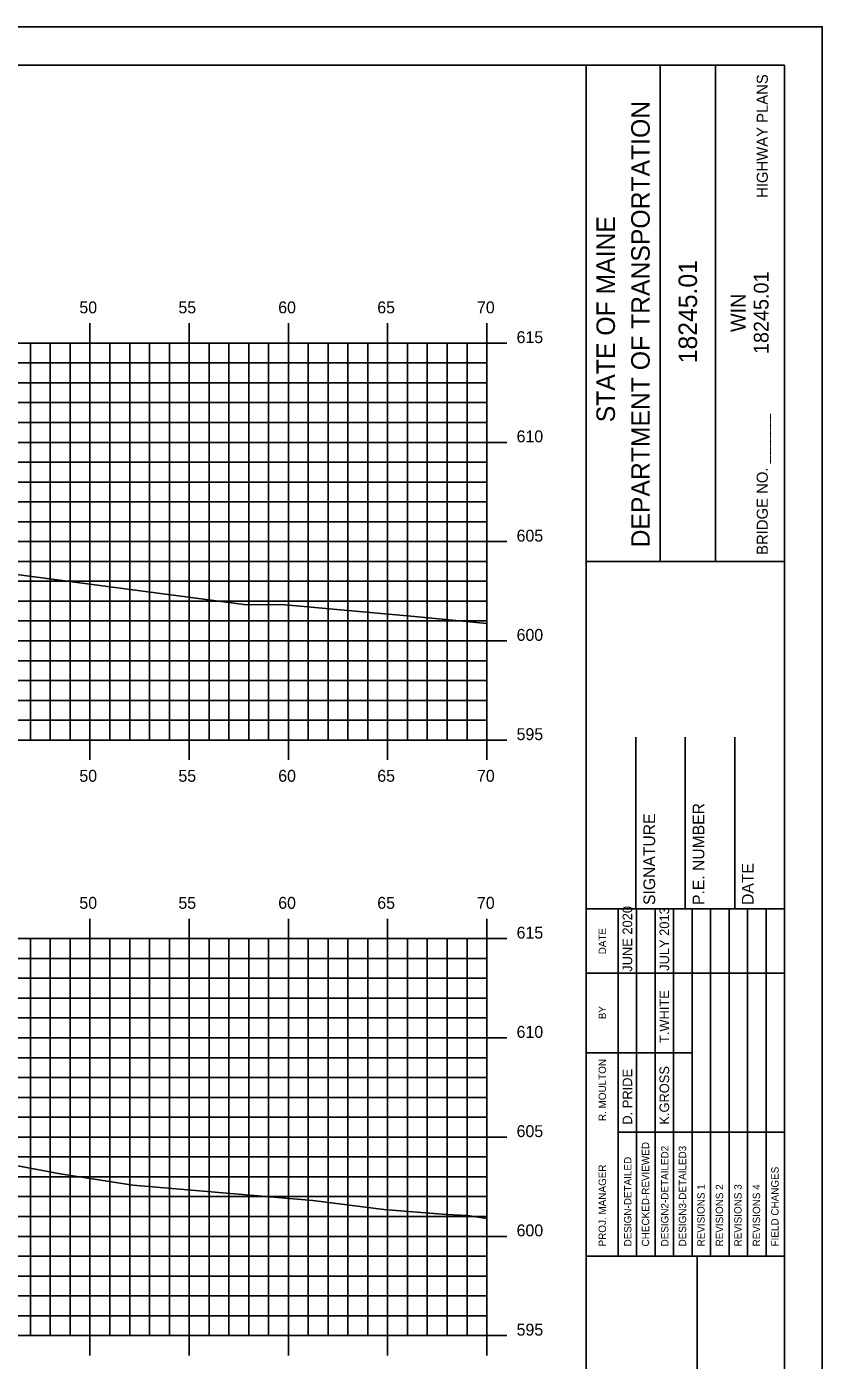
# Model space of a CAD drawing. Extents: x 1048362 to 1048532, y 780904 to 781014.
# Drawn here: x 1048492.3 to 1048532.4, y 780946.9 to 781014.1 of the extents above; entities that cross this region are included whole.
import ezdxf

# ---------------------------------------------------------------- set-up
doc = ezdxf.new("R2010")
doc.units = 0
for name, color, linetype in [('BORDER', 7, 'Continuous'), ('Default', 7, 'Continuous'), ('H_V ANNOTATION', 7, 'Continuous'), ('MAJOR', 7, 'Continuous'), ('MINOR', 7, 'Continuous'), ('S_Roadway_Centerline', 7, 'Continuous')]:
    doc.layers.add(name, color=color, linetype=linetype)

msp = doc.modelspace()

# ---------------------------------------------------------------- linework, layer by layer
at = {"layer": 'Default'}
for p, q in [((1048530.47, 781012.114), (1048370.47, 781012.114)), ((1048520.47, 780907.114), (1048520.47, 781012.117)), ((1048524.198, 780987.111), (1048524.198, 781012.111)), ((1048526.993, 780987.111), (1048526.993, 781012.111)), ((1048530.47, 780907.114), (1048530.47, 781012.114)), ((1048520.471, 780987.108), (1048530.47, 780987.108)), ((1048522.97, 780969.617), (1048522.97, 780978.265)), ((1048525.47, 780969.617), (1048525.47, 780978.265)), ((1048527.97, 780969.617), (1048527.97, 780978.265)), ((1048520.47, 780969.617), (1048530.47, 780969.617)), ((1048520.47, 780952.117), (1048530.47, 780952.117)), ((1048526.061, 780917.117), (1048526.061, 780952.117))]:
    msp.add_line(p, q, dxfattribs=at)
msp.add_lwpolyline([(1048362.376, 780904.055), (1048532.376, 780904.055), (1048532.376, 781014.055), (1048362.376, 781014.055)], close=True, dxfattribs=at)
for points in [[(1048522.085, 780966.367), (1048522.085, 780969.617)], [(1048523.017, 780952.12), (1048523.017, 780969.617)], [(1048523.949, 780969.617), (1048523.949, 780952.12)], [(1048524.88, 780952.12), (1048524.88, 780969.617)], [(1048525.812, 780952.12), (1048525.812, 780969.617)], [(1048526.744, 780952.12), (1048526.744, 780969.617)], [(1048527.676, 780952.12), (1048527.676, 780969.617)], [(1048528.607, 780952.12), (1048528.607, 780969.617)], [(1048529.539, 780952.12), (1048529.539, 780969.617)], [(1048522.085, 780952.12), (1048522.085, 780968.911)], [(1048520.47, 780966.367), (1048530.47, 780966.367)], [(1048520.47, 780962.367), (1048522.085, 780962.367)], [(1048522.085, 780962.367), (1048525.811, 780962.367)], [(1048522.085, 780958.367), (1048530.47, 780958.367)]]:
    msp.add_lwpolyline(points, dxfattribs=at)
at = {"layer": 'MAJOR'}
for p, q in [((1048495.469, 780999.116), (1048495.469, 780998.114)), ((1048500.469, 780999.116), (1048500.469, 780998.114)), ((1048505.469, 780999.116), (1048505.469, 780998.114)), ((1048510.469, 780999.116), (1048510.469, 780998.114)), ((1048515.469, 780999.116), (1048515.469, 780998.114)), ((1048375.469, 780998.114), (1048515.469, 780998.114)), ((1048375.469, 780998.114), (1048515.469, 780998.114)), ((1048495.469, 780978.114), (1048495.469, 780998.114)), ((1048500.469, 780978.114), (1048500.469, 780998.114)), ((1048505.469, 780978.114), (1048505.469, 780998.114)), ((1048510.469, 780978.114), (1048510.469, 780998.114)), ((1048516.471, 780998.114), (1048514.467, 780998.114)), ((1048515.469, 780978.114), (1048515.469, 780998.114)), ((1048515.469, 780978.114), (1048515.469, 780998.114)), ((1048375.469, 780993.114), (1048515.469, 780993.114)), ((1048516.471, 780993.114), (1048514.467, 780993.114)), ((1048375.469, 780988.114), (1048515.469, 780988.114)), ((1048516.471, 780988.114), (1048514.467, 780988.114)), ((1048375.469, 780983.114), (1048515.469, 780983.114)), ((1048516.471, 780983.114), (1048514.467, 780983.114)), ((1048375.469, 780978.114), (1048515.469, 780978.114)), ((1048375.469, 780978.114), (1048515.469, 780978.114)), ((1048495.469, 780977.112), (1048495.469, 780978.114)), ((1048500.469, 780977.112), (1048500.469, 780978.114)), ((1048505.469, 780977.112), (1048505.469, 780978.114)), ((1048510.469, 780977.112), (1048510.469, 780978.114)), ((1048516.471, 780978.114), (1048514.467, 780978.114)), ((1048515.469, 780977.112), (1048515.469, 780978.114)), ((1048495.469, 780969.116), (1048495.469, 780968.114)), ((1048500.469, 780969.116), (1048500.469, 780968.114)), ((1048505.469, 780969.116), (1048505.469, 780968.114)), ((1048510.469, 780969.116), (1048510.469, 780968.114)), ((1048515.469, 780969.116), (1048515.469, 780968.114)), ((1048375.469, 780968.114), (1048515.469, 780968.114)), ((1048375.469, 780968.114), (1048515.469, 780968.114)), ((1048495.469, 780948.114), (1048495.469, 780968.114)), ((1048500.469, 780948.114), (1048500.469, 780968.114)), ((1048505.469, 780948.114), (1048505.469, 780968.114)), ((1048510.469, 780948.114), (1048510.469, 780968.114)), ((1048516.471, 780968.114), (1048514.467, 780968.114)), ((1048515.469, 780948.114), (1048515.469, 780968.114)), ((1048515.469, 780948.114), (1048515.469, 780968.114)), ((1048375.469, 780963.114), (1048515.469, 780963.114)), ((1048516.471, 780963.114), (1048514.467, 780963.114)), ((1048375.469, 780958.114), (1048515.469, 780958.114)), ((1048516.471, 780958.114), (1048514.467, 780958.114)), ((1048375.469, 780953.114), (1048515.469, 780953.114)), ((1048516.471, 780953.114), (1048514.467, 780953.114)), ((1048375.469, 780948.114), (1048515.469, 780948.114)), ((1048375.469, 780948.114), (1048515.469, 780948.114)), ((1048495.469, 780947.112), (1048495.469, 780948.114)), ((1048500.469, 780947.112), (1048500.469, 780948.114)), ((1048505.469, 780947.112), (1048505.469, 780948.114)), ((1048510.469, 780947.112), (1048510.469, 780948.114)), ((1048516.471, 780948.114), (1048514.467, 780948.114)), ((1048515.469, 780947.112), (1048515.469, 780948.114))]:
    msp.add_line(p, q, dxfattribs=at)
at = {"layer": 'MINOR'}
for p, q in [((1048492.469, 780978.114), (1048492.469, 780998.114)), ((1048493.469, 780978.114), (1048493.469, 780998.114)), ((1048494.469, 780978.114), (1048494.469, 780998.114)), ((1048496.469, 780978.114), (1048496.469, 780998.114)), ((1048497.469, 780978.114), (1048497.469, 780998.114)), ((1048498.469, 780978.114), (1048498.469, 780998.114)), ((1048499.469, 780978.114), (1048499.469, 780998.114)), ((1048501.469, 780978.114), (1048501.469, 780998.114)), ((1048502.469, 780978.114), (1048502.469, 780998.114)), ((1048503.469, 780978.114), (1048503.469, 780998.114)), ((1048504.469, 780978.114), (1048504.469, 780998.114)), ((1048506.469, 780978.114), (1048506.469, 780998.114)), ((1048507.469, 780978.114), (1048507.469, 780998.114)), ((1048508.469, 780978.114), (1048508.469, 780998.114)), ((1048509.469, 780978.114), (1048509.469, 780998.114)), ((1048511.469, 780978.114), (1048511.469, 780998.114)), ((1048512.469, 780978.114), (1048512.469, 780998.114)), ((1048513.469, 780978.114), (1048513.469, 780998.114)), ((1048514.469, 780978.114), (1048514.469, 780998.114)), ((1048375.469, 780997.114), (1048515.469, 780997.114)), ((1048515.469, 780997.114), (1048514.467, 780997.114)), ((1048375.469, 780996.114), (1048515.469, 780996.114)), ((1048515.469, 780996.114), (1048514.467, 780996.114)), ((1048375.469, 780995.114), (1048515.469, 780995.114)), ((1048515.469, 780995.114), (1048514.467, 780995.114)), ((1048375.469, 780994.114), (1048515.469, 780994.114)), ((1048515.469, 780994.114), (1048514.467, 780994.114)), ((1048375.469, 780992.114), (1048515.469, 780992.114)), ((1048515.469, 780992.114), (1048514.467, 780992.114)), ((1048375.469, 780991.114), (1048515.469, 780991.114)), ((1048515.469, 780991.114), (1048514.467, 780991.114)), ((1048375.469, 780990.114), (1048515.469, 780990.114)), ((1048515.469, 780990.114), (1048514.467, 780990.114)), ((1048375.469, 780989.114), (1048515.469, 780989.114)), ((1048515.469, 780989.114), (1048514.467, 780989.114)), ((1048375.469, 780987.114), (1048515.469, 780987.114)), ((1048515.469, 780987.114), (1048514.467, 780987.114)), ((1048375.469, 780986.114), (1048515.469, 780986.114)), ((1048515.469, 780986.114), (1048514.467, 780986.114)), ((1048375.469, 780985.114), (1048515.469, 780985.114)), ((1048515.469, 780985.114), (1048514.467, 780985.114)), ((1048375.469, 780984.114), (1048515.469, 780984.114)), ((1048515.469, 780984.114), (1048514.467, 780984.114)), ((1048375.469, 780982.114), (1048515.469, 780982.114)), ((1048515.469, 780982.114), (1048514.467, 780982.114)), ((1048375.469, 780981.114), (1048515.469, 780981.114)), ((1048515.469, 780981.114), (1048514.467, 780981.114)), ((1048375.469, 780980.114), (1048515.469, 780980.114)), ((1048515.469, 780980.114), (1048514.467, 780980.114)), ((1048375.469, 780979.114), (1048515.469, 780979.114)), ((1048515.469, 780979.114), (1048514.467, 780979.114)), ((1048492.469, 780948.114), (1048492.469, 780968.114)), ((1048493.469, 780948.114), (1048493.469, 780968.114)), ((1048494.469, 780948.114), (1048494.469, 780968.114)), ((1048496.469, 780948.114), (1048496.469, 780968.114)), ((1048497.469, 780948.114), (1048497.469, 780968.114)), ((1048498.469, 780948.114), (1048498.469, 780968.114)), ((1048499.469, 780948.114), (1048499.469, 780968.114)), ((1048501.469, 780948.114), (1048501.469, 780968.114)), ((1048502.469, 780948.114), (1048502.469, 780968.114)), ((1048503.469, 780948.114), (1048503.469, 780968.114)), ((1048504.469, 780948.114), (1048504.469, 780968.114)), ((1048506.469, 780948.114), (1048506.469, 780968.114)), ((1048507.469, 780948.114), (1048507.469, 780968.114)), ((1048508.469, 780948.114), (1048508.469, 780968.114)), ((1048509.469, 780948.114), (1048509.469, 780968.114)), ((1048511.469, 780948.114), (1048511.469, 780968.114)), ((1048512.469, 780948.114), (1048512.469, 780968.114)), ((1048513.469, 780948.114), (1048513.469, 780968.114)), ((1048514.469, 780948.114), (1048514.469, 780968.114)), ((1048375.469, 780967.114), (1048515.469, 780967.114)), ((1048515.469, 780967.114), (1048514.467, 780967.114)), ((1048375.469, 780966.114), (1048515.469, 780966.114)), ((1048515.469, 780966.114), (1048514.467, 780966.114)), ((1048375.469, 780965.114), (1048515.469, 780965.114)), ((1048515.469, 780965.114), (1048514.467, 780965.114)), ((1048375.469, 780964.114), (1048515.469, 780964.114)), ((1048515.469, 780964.114), (1048514.467, 780964.114)), ((1048375.469, 780962.114), (1048515.469, 780962.114)), ((1048515.469, 780962.114), (1048514.467, 780962.114)), ((1048375.469, 780961.114), (1048515.469, 780961.114)), ((1048515.469, 780961.114), (1048514.467, 780961.114)), ((1048375.469, 780960.114), (1048515.469, 780960.114)), ((1048515.469, 780960.114), (1048514.467, 780960.114)), ((1048375.469, 780959.114), (1048515.469, 780959.114)), ((1048515.469, 780959.114), (1048514.467, 780959.114)), ((1048375.469, 780957.114), (1048515.469, 780957.114)), ((1048515.469, 780957.114), (1048514.467, 780957.114)), ((1048375.469, 780956.114), (1048515.469, 780956.114)), ((1048515.469, 780956.114), (1048514.467, 780956.114)), ((1048375.469, 780955.114), (1048515.469, 780955.114)), ((1048515.469, 780955.114), (1048514.467, 780955.114)), ((1048375.469, 780954.114), (1048515.469, 780954.114)), ((1048515.469, 780954.114), (1048514.467, 780954.114)), ((1048375.469, 780952.114), (1048515.469, 780952.114)), ((1048515.469, 780952.114), (1048514.467, 780952.114)), ((1048375.469, 780951.114), (1048515.469, 780951.114)), ((1048515.469, 780951.114), (1048514.467, 780951.114)), ((1048375.469, 780950.114), (1048515.469, 780950.114)), ((1048515.469, 780950.114), (1048514.467, 780950.114)), ((1048375.469, 780949.114), (1048515.469, 780949.114)), ((1048515.469, 780949.114), (1048514.467, 780949.114))]:
    msp.add_line(p, q, dxfattribs=at)
at = {"layer": 'S_Roadway_Centerline'}
for points in [[(1048422.46, 780988.888), (1048429.469, 780989.042), (1048431.683, 780988.93), (1048432.503, 780988.86), (1048434.037, 780988.719), (1048435.915, 780988.883), (1048436.697, 780989.006), (1048436.755, 780989.005), (1048442.99, 780989.373), (1048447.66, 780989.639), (1048452.523, 780989.5), (1048458.14, 780989.526), (1048460.67, 780989.466), (1048463.798, 780989.309), (1048468.977, 780989.026), (1048472.406, 780987.632), (1048476.081, 780987.522), (1048479.697, 780987.307), (1048490.358, 780986.648), (1048503.356, 780984.928), (1048505.12, 780984.938), (1048511.821, 780984.344), (1048515.469, 780983.985)], [(1048489.666, 780957.071), (1048493.958, 780956.257), (1048497.624, 780955.686), (1048506.699, 780954.915), (1048510.281, 780954.46), (1048513.416, 780954.215), (1048514.49, 780954.159), (1048515.469, 780954.016)]]:
    msp.add_lwpolyline(points, dxfattribs=at)

# ---------------------------------------------------------------- texts
at = {"layer": 'BORDER'}
for s, p in [('DEPARTMENT OF TRANSPORTATION', (1048523.676, 780987.82)), ('STATE OF MAINE', (1048521.925, 780994.126))]:
    msp.add_text(s, height=0.93176, rotation=90, dxfattribs=at).set_placement(p)
at = {"layer": 'Default'}
for s, height, p in [('HIGHWAY PLANS', 0.55901, (1048529.628, 781005.43)), ('18245.01', 0.9318, (1048526.062, 780997.099)), ('18245.01', 0.7453, (1048529.665, 780997.564)), ('WIN', 0.7453, (1048528.506, 780998.672)), ('BRIDGE NO. ______', 0.55901, (1048529.628, 780987.445)), ('P.E. NUMBER', 0.59055, (1048526.43, 780969.809)), ('SIGNATURE', 0.5906, (1048523.95, 780969.809)), ('DATE', 0.5906, (1048528.911, 780969.809)), ('JUNE 2020', 0.4845, (1048522.793, 780966.442)), ('JULY 2013', 0.4845, (1048524.656, 780966.489)), ('DATE', 0.3714, (1048521.474, 780967.323)), ('T.WHITE', 0.4845, (1048524.656, 780962.852)), ('BY', 0.3714, (1048521.474, 780964.052)), ('R. MOULTON', 0.3727, (1048521.474, 780958.92)), ('D. PRIDE', 0.4845, (1048522.793, 780958.74)), ('K.GROSS', 0.4845, (1048524.656, 780958.74)), ('CHECKED-REVIEWED', 0.37275, (1048523.651, 780952.605)), ('DESIGN2-DETAILED2', 0.37275, (1048524.62, 780952.605)), ('DESIGN3-DETAILED3', 0.37275, (1048525.514, 780952.605)), ('PROJ. MANAGER', 0.37275, (1048521.474, 780952.605)), ('DESIGN-DETAILED', 0.37275, (1048522.756, 780952.605)), ('FIELD CHANGES', 0.37275, (1048530.172, 780952.605)), ('REVISIONS 1', 0.37275, (1048526.446, 780952.605)), ('REVISIONS 2', 0.37275, (1048527.377, 780952.605)), ('REVISIONS 3', 0.37275, (1048528.309, 780952.605)), ('REVISIONS 4', 0.37275, (1048529.241, 780952.605))]:
    msp.add_text(s, height=height, rotation=90, dxfattribs=at).set_placement(p)
at = {"layer": 'H_V ANNOTATION'}
for s, p in [('50', (1048494.934, 780999.614)), ('55', (1048499.926, 780999.614)), ('60', (1048504.956, 780999.614)), ('65', (1048509.948, 780999.614)), ('70', (1048514.972, 780999.614)), ('615', (1048516.969, 780998.114)), ('610', (1048516.969, 780993.114)), ('605', (1048516.969, 780988.114)), ('600', (1048516.969, 780983.114)), ('595', (1048516.969, 780978.114)), ('50', (1048494.934, 780976.014)), ('55', (1048499.926, 780976.014)), ('60', (1048504.956, 780976.014)), ('65', (1048509.948, 780976.014)), ('70', (1048514.972, 780976.014)), ('50', (1048494.934, 780969.614)), ('55', (1048499.926, 780969.614)), ('60', (1048504.956, 780969.614)), ('65', (1048509.948, 780969.614)), ('70', (1048514.972, 780969.614)), ('615', (1048516.969, 780968.114)), ('610', (1048516.969, 780963.114)), ('605', (1048516.969, 780958.114)), ('600', (1048516.969, 780953.114)), ('595', (1048516.969, 780948.114))]:
    msp.add_text(s, height=0.6, dxfattribs=at).set_placement(p)

doc.saveas('drawing.dxf')
